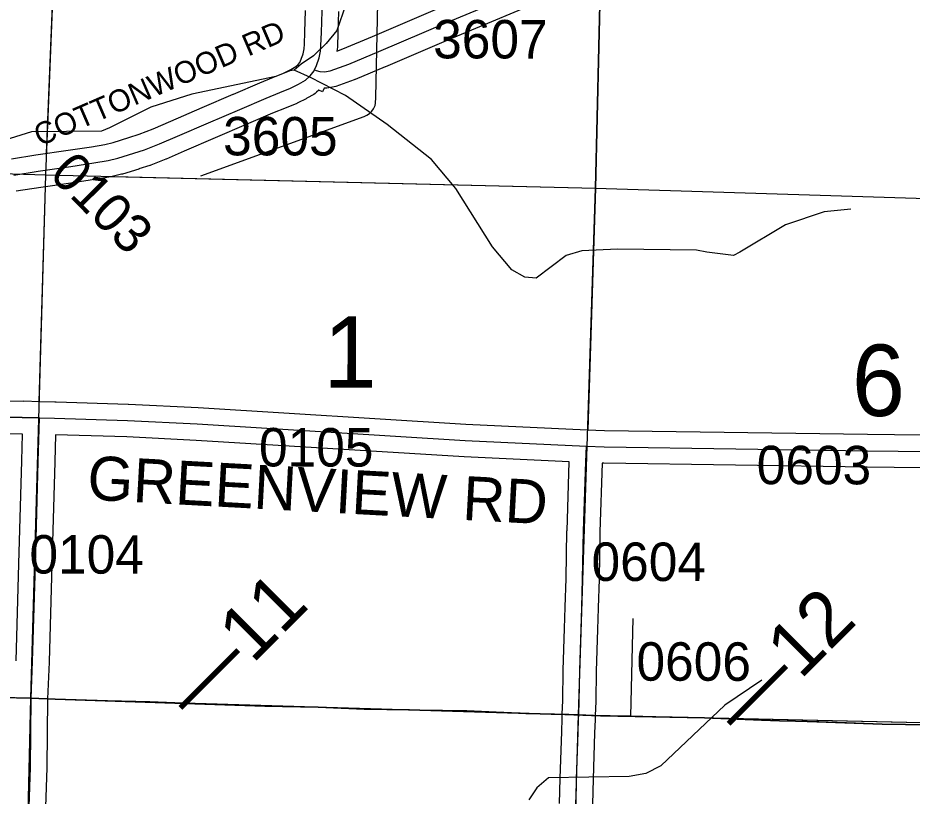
# Model space of a CAD drawing. Extents: x -132.8 to -73.3, y -60 to -26.
# Drawn here: x -117 to -115.373, y -51.589 to -50.173 of the extents above; entities that cross this region are included whole.
import ezdxf

# ---------------------------------------------------------------- set-up
doc = ezdxf.new("R2010")
doc.units = 0
for name, color, linetype in [('tdCoDirctArrow', 7, 'Continuous'), ('tdCoHydroRiver', 7, 'Continuous'), ('tdCoPriCL', 7, 'Continuous'), ('tdCoPrimary', 7, 'Continuous'), ('tdCoPriNonDiv', 7, 'Continuous'), ('tdCoPriNonDivCL', 7, 'Continuous'), ('tdCoSecRdNmbr', 7, 'Continuous'), ('tdCoSecRdTxt', 7, 'Continuous'), ('tdCoSecRteBand', 7, 'Continuous'), ('tdCoSecRteCL', 7, 'Continuous'), ('tdCoSectLine', 7, 'Continuous'), ('tdCoSectLinePart', 7, 'Continuous'), ('tdCoSectNmbr', 7, 'Continuous'), ('tdCoSurfBitum', 7, 'Continuous'), ('tdCoSurfConc', 7, 'Continuous'), ('tdCoSurfConcUnbanded', 7, 'Continuous'), ('tdCoSurfGravel', 7, 'Continuous'), ('tdCoTwpBndry', 7, 'Continuous'), ('tdCoTwpBndryShd', 7, 'Continuous'), ('tdStHwyPriRefPost1', 7, 'Continuous')]:
    doc.layers.add(name, color=color, linetype=linetype)

msp = doc.modelspace()

# ---------------------------------------------------------------- linework, layer by layer
at = {"layer": 'tdCoDirctArrow'}
msp.add_lwpolyline([(-116.6676, -50.4602), (-116.3705, -50.3525), (-116.3655, -50.3502), (-116.3604, -50.3469), (-116.3565, -50.3431), (-116.3534, -50.3385), (-116.3504, -50.3326), (-116.3493, -50.328), (-116.3487, -50.318), (-116.3404, -49.9157)], dxfattribs=at)
at = {"layer": 'tdCoHydroRiver'}
for points in [[(-116.3926, -50.1164), (-116.4199, -50.1962), (-116.4396, -50.2199)], [(-116.4396, -50.2199), (-116.4624, -50.242), (-116.4849, -50.2572), (-116.4978, -50.268)], [(-116.4978, -50.268), (-116.5057, -50.2693), (-116.5312, -50.2797), (-116.6836, -50.3121), (-116.7583, -50.3355), (-116.8335, -50.373), (-116.8478, -50.3789), (-116.9757, -50.3804), (-117.0552, -50.4052), (-117.1027, -50.4087), (-117.1495, -50.4121)], [(-115.4846, -50.521), (-115.5336, -50.526), (-115.6037, -50.5495), (-115.687, -50.5994), (-115.6982, -50.6055), (-115.747, -50.5995), (-115.7658, -50.5958), (-115.9094, -50.5938), (-115.9742, -50.5968), (-116.0028, -50.6056), (-116.0575, -50.6468), (-116.078, -50.6447), (-116.1013, -50.6315), (-116.1366, -50.5896), (-116.2033, -50.4837), (-116.2478, -50.4305), (-116.3282, -50.3669), (-116.4043, -50.3145), (-116.4681, -50.2813), (-116.4978, -50.268)], [(-115.6468, -51.3783), (-115.7142, -51.4239), (-115.8306, -51.5345), (-115.8578, -51.548), (-115.8879, -51.5536), (-116.0348, -51.5561), (-116.0558, -51.5745), (-116.0705, -51.5962)]]:
    msp.add_lwpolyline(points, dxfattribs=at)
at = {"layer": 'tdCoPriCL'}
msp.add_lwpolyline([(-115.3428, -51.4598), (-115.4279, -51.4583), (-115.4925, -51.4561), (-115.5433, -51.4543), (-115.5854, -51.453), (-115.6148, -51.4521), (-115.6473, -51.451), (-115.7512, -51.4472), (-115.8397, -51.445), (-115.886, -51.4441), (-115.9401, -51.443), (-115.9802, -51.4416), (-115.998, -51.441), (-116.076, -51.4388), (-116.1832, -51.4339), (-116.2277, -51.4334), (-116.2691, -51.4329), (-116.288, -51.4325), (-116.3699, -51.4309), (-116.4538, -51.4275), (-116.5504, -51.4257), (-116.5507, -51.4255), (-116.654, -51.4218), (-116.7601, -51.4179), (-116.837, -51.4159), (-116.9322, -51.4129), (-116.9767, -51.4114), (-117.0027, -51.4105)], dxfattribs=at)
at = {"layer": 'tdCoPrimary'}
for p, q in [((-115.5851, -51.453), (-115.5429, -51.4543)), ((-115.5851, -51.453), (-115.5429, -51.4543)), ((-115.5429, -51.4543), (-115.4921, -51.4561)), ((-115.5429, -51.4543), (-115.4921, -51.4561))]:
    msp.add_line(p, q, dxfattribs=at)
for points in [[(-117.0764, -51.407), (-117.0475, -51.4082), (-117.0023, -51.4105), (-116.9763, -51.4114), (-116.9318, -51.4129), (-116.8366, -51.4159), (-116.8031, -51.4167)], [(-117.0764, -51.407), (-117.0475, -51.4082), (-117.0023, -51.4105), (-116.9763, -51.4114), (-116.9318, -51.4129), (-116.8366, -51.4159), (-116.8031, -51.4167)], [(-117.0023, -51.4105), (-116.9763, -51.4114), (-116.9318, -51.4129), (-116.8366, -51.4159), (-116.8031, -51.4167), (-116.7597, -51.4179), (-116.6536, -51.4218), (-116.5501, -51.4257), (-116.5503, -51.4255), (-116.4534, -51.4275), (-116.3695, -51.4309), (-116.2876, -51.4325), (-116.2687, -51.4329), (-116.2274, -51.4334), (-116.1829, -51.4339), (-116.0756, -51.4388), (-115.9977, -51.441), (-115.9799, -51.4416), (-115.9397, -51.443), (-115.8848, -51.4441), (-115.8393, -51.445), (-115.7508, -51.4472), (-115.6469, -51.451), (-115.6144, -51.4521), (-115.5851, -51.453), (-115.5429, -51.4543), (-115.4921, -51.4561), (-115.4275, -51.4583), (-115.3424, -51.4598)], [(-116.8031, -51.4167), (-116.7597, -51.4179), (-116.6536, -51.4218), (-116.5501, -51.4257), (-116.5503, -51.4255), (-116.4534, -51.4275), (-116.3695, -51.4309), (-116.2876, -51.4325)], [(-116.8031, -51.4167), (-116.7597, -51.4179), (-116.6536, -51.4218), (-116.5501, -51.4257), (-116.5503, -51.4255), (-116.4534, -51.4275), (-116.3695, -51.4309), (-116.2876, -51.4325)], [(-116.2876, -51.4325), (-116.2687, -51.4329), (-116.2274, -51.4334)], [(-116.2876, -51.4325), (-116.2687, -51.4329), (-116.2274, -51.4334)], [(-116.2274, -51.4334), (-116.1829, -51.4339), (-116.0756, -51.4388), (-115.9977, -51.441), (-115.9799, -51.4416), (-115.9397, -51.443), (-115.8848, -51.4441), (-115.8393, -51.445), (-115.7508, -51.4472), (-115.6469, -51.451)], [(-116.2274, -51.4334), (-116.1829, -51.4339), (-116.0756, -51.4388), (-115.9977, -51.441), (-115.9799, -51.4416), (-115.9397, -51.443), (-115.8848, -51.4441), (-115.8393, -51.445), (-115.7508, -51.4472), (-115.6469, -51.451)], [(-115.6469, -51.451), (-115.6144, -51.4521), (-115.5851, -51.453)], [(-115.6469, -51.451), (-115.6144, -51.4521), (-115.5851, -51.453)], [(-115.4921, -51.4561), (-115.4275, -51.4583), (-115.3424, -51.4598), (-115.2524, -51.461), (-115.173, -51.4608), (-115.173, -51.4608)], [(-115.4921, -51.4561), (-115.4275, -51.4583), (-115.3424, -51.4598), (-115.2524, -51.461), (-115.173, -51.4608), (-115.173, -51.4608)]]:
    msp.add_lwpolyline(points, dxfattribs=at)
at = {"layer": 'tdCoPriNonDiv'}
msp.add_lwpolyline([(-119.3781, -51.323), (-119.2533, -51.3338), (-119.178, -51.3375), (-119.0616, -51.3419), (-118.9287, -51.352), (-118.8478, -51.3564), (-118.7115, -51.3584), (-118.5248, -51.3661), (-118.2991, -51.3705), (-118.0533, -51.3794), (-117.7549, -51.3875), (-117.6523, -51.392), (-117.5499, -51.3934), (-117.3443, -51.4013), (-117.1376, -51.4043), (-116.9322, -51.4129), (-116.5507, -51.4255), (-116.4538, -51.4275), (-116.2691, -51.4329), (-116.1832, -51.4339), (-115.9401, -51.443), (-115.7512, -51.4472), (-115.4279, -51.4583), (-115.2528, -51.461)], dxfattribs=at)
at = {"layer": 'tdCoPriNonDivCL'}
msp.add_lwpolyline([(-117.0027, -51.4105), (-116.9767, -51.4114), (-116.9322, -51.4129), (-116.837, -51.4159), (-116.8035, -51.4167), (-116.7601, -51.4179), (-116.654, -51.4218), (-116.5504, -51.4257), (-116.5507, -51.4255), (-116.4538, -51.4275), (-116.3699, -51.4309), (-116.288, -51.4325), (-116.2691, -51.4329), (-116.2277, -51.4334), (-116.1832, -51.4339), (-116.076, -51.4388), (-115.998, -51.441), (-115.9802, -51.4416), (-115.9401, -51.443), (-115.8852, -51.4441), (-115.8397, -51.445), (-115.7512, -51.4472), (-115.6473, -51.451), (-115.6148, -51.4521), (-115.5854, -51.453), (-115.5433, -51.4543), (-115.4925, -51.4561), (-115.4279, -51.4583), (-115.3428, -51.4598)], dxfattribs=at)
msp.add_lwpolyline([(-117.0027, -51.4105), (-116.9767, -51.4114), (-116.9322, -51.4129), (-116.837, -51.4159), (-116.8035, -51.4167), (-116.7601, -51.4179), (-116.654, -51.4218), (-116.5504, -51.4257), (-116.5507, -51.4255), (-116.4538, -51.4275), (-116.3699, -51.4309), (-116.288, -51.4325), (-116.2691, -51.4329), (-116.2277, -51.4334), (-116.1832, -51.4339), (-116.076, -51.4388), (-115.998, -51.441), (-115.9802, -51.4416), (-115.9401, -51.443), (-115.8852, -51.4441), (-115.8397, -51.445), (-115.7512, -51.4472), (-115.6473, -51.451), (-115.6148, -51.4521), (-115.5854, -51.453), (-115.5433, -51.4543), (-115.4925, -51.4561), (-115.4279, -51.4583), (-115.3428, -51.4598)], dxfattribs=at)
at = {"layer": 'tdCoSecRteBand'}
for points in [[(-116.0284, -50.1337), (-116.2083, -50.2091), (-116.3315, -50.2619), (-116.3316, -50.2619), (-116.3317, -50.2619), (-116.3867, -50.2851), (-116.3874, -50.2854), (-116.3882, -50.2857), (-116.422, -50.2978), (-116.4248, -50.2988), (-116.4278, -50.2992), (-116.4379, -50.3007), (-116.4409, -50.3012), (-116.4429, -50.301), (-116.446, -50.3076), (-116.4526, -50.3046), (-116.457, -50.3085), (-116.4593, -50.3106), (-116.462, -50.3122), (-116.4746, -50.3194), (-116.4753, -50.3198), (-116.476, -50.3201), (-116.4907, -50.3276), (-116.4918, -50.3281), (-116.4929, -50.3286), (-116.5123, -50.3366), (-116.5367, -50.3467), (-116.5848, -50.3672), (-116.6415, -50.3913), (-116.6979, -50.4157), (-116.7303, -50.4299), (-116.7308, -50.4302), (-116.7313, -50.4304), (-116.7586, -50.4411), (-116.7595, -50.4415), (-116.7604, -50.4417), (-116.7799, -50.448), (-116.7801, -50.4481), (-116.7803, -50.4481), (-116.8098, -50.4572), (-116.8106, -50.4574), (-116.8115, -50.4576), (-116.8289, -50.4619), (-116.83, -50.4622), (-116.8311, -50.4624), (-116.8567, -50.4667), (-116.8569, -50.4667), (-116.8572, -50.4668), (-116.8996, -50.4732), (-116.8996, -50.4732), (-116.8997, -50.4732), (-116.9587, -50.4819), (-117.0031, -50.4887)], [(-116.4197, -50.2333), (-116.4092, -50.2295), (-116.3551, -50.2067), (-116.2318, -50.1539)], [(-117.012, -50.4294), (-116.9677, -50.4225), (-116.9676, -50.4225), (-116.9675, -50.4225), (-116.9085, -50.4138), (-116.8664, -50.4075), (-116.8422, -50.4034), (-116.8266, -50.3996), (-116.7981, -50.3908), (-116.7797, -50.3849), (-116.7538, -50.3747), (-116.7219, -50.3607), (-116.7218, -50.3607), (-116.7218, -50.3607), (-116.6652, -50.3362), (-116.6652, -50.3362), (-116.6651, -50.3362), (-116.6083, -50.312), (-116.6083, -50.3119), (-116.6082, -50.3119), (-116.56, -50.2915), (-116.5599, -50.2914), (-116.5598, -50.2914), (-116.5353, -50.2811), (-116.5352, -50.2811), (-116.5351, -50.2811), (-116.5168, -50.2736), (-116.5038, -50.267), (-116.4947, -50.2617), (-116.4901, -50.2576), (-116.4873, -50.2541), (-116.4819, -50.2403), (-116.4813, -50.2385), (-116.4796, -50.2292), (-116.4787, -50.2209), (-116.4779, -50.1988), (-116.4769, -50.1598)], [(-116.4169, -50.1613), (-116.4179, -50.2005), (-116.4179, -50.2007), (-116.4179, -50.2008), (-116.4188, -50.2243), (-116.4188, -50.2254), (-116.419, -50.2265), (-116.4197, -50.2333)], [(-117.2149, -50.8661), (-116.9899, -50.8705), (-116.9899, -50.8702), (-116.9601, -50.8711), (-116.9332, -50.8716), (-116.9331, -50.8716), (-116.9331, -50.8716), (-116.9303, -50.8716), (-116.9303, -50.8717), (-116.7997, -50.8758), (-116.7995, -50.8758), (-116.7992, -50.8758), (-116.6724, -50.882), (-116.6722, -50.882), (-116.672, -50.882), (-116.185, -50.9123), (-115.9648, -50.9227), (-115.933, -50.9237), (-115.4544, -50.9308), (-115.0098, -50.936)], [(-117.0033, -51.3432), (-116.9984, -51.1668), (-116.9932, -50.9794), (-116.9932, -50.9794), (-116.9932, -50.9793), (-116.9918, -50.9305), (-117.216, -50.9261)], [(-116.0148, -51.6028), (-116.0138, -51.5573), (-116.0138, -51.5572), (-116.0138, -51.557), (-116.0109, -51.4725), (-116.0101, -51.4484), (-116.0101, -51.4484), (-116.0101, -51.4483), (-116.0098, -51.4405), (-116.0089, -51.4153), (-116.0079, -51.3605), (-116.0079, -51.3603), (-116.0079, -51.3601), (-116.0056, -51.2844), (-116.0056, -51.2844), (-116.0056, -51.2844), (-116.0043, -51.2453), (-116.0029, -51.1932), (-116.0012, -51.1068), (-116.0012, -51.1066), (-116.0011, -51.1064), (-115.9972, -50.9812), (-116.188, -50.9722), (-116.1882, -50.9722), (-116.1885, -50.9722), (-116.6756, -50.9419), (-116.8019, -50.9357), (-116.9318, -50.9316), (-116.9332, -50.9811), (-116.9384, -51.1685), (-116.9384, -51.1685), (-116.9384, -51.1685), (-116.9434, -51.3451), (-116.9434, -51.3453), (-116.9434, -51.3456), (-116.9463, -51.4121), (-116.9473, -51.5373), (-116.9473, -51.5377), (-116.9473, -51.5381), (-116.9535, -51.7158)], [(-115.0105, -50.996), (-115.4551, -50.9908), (-115.4552, -50.9908), (-115.4552, -50.9908), (-115.9342, -50.9836), (-115.9344, -50.9836), (-115.9346, -50.9836), (-115.9372, -50.9836), (-115.9412, -51.1082), (-115.9429, -51.1945), (-115.9429, -51.1946), (-115.9429, -51.1947), (-115.9444, -51.247), (-115.9444, -51.2471), (-115.9444, -51.2471), (-115.9456, -51.2863), (-115.9479, -51.3618), (-115.9489, -51.4167), (-115.9489, -51.4169), (-115.9489, -51.4172), (-115.9499, -51.4427), (-115.9502, -51.4505), (-115.951, -51.4745), (-115.9538, -51.5588), (-115.9548, -51.6042)]]:
    msp.add_lwpolyline(points, dxfattribs=at)
at = {"layer": 'tdCoSecRteCL'}
msp.add_line((-115.8848, -51.4441), (-115.8808, -51.2659), dxfattribs=at)
for points in [[(-116.4605, -50.2677), (-116.4567, -50.2597), (-116.4521, -50.2459), (-116.4499, -50.2335), (-116.4488, -50.2232), (-116.4479, -50.1997), (-116.4469, -50.1605), (-116.4441, -50.0442), (-116.4426, -49.9917), (-116.4395, -49.8758), (-116.4376, -49.8162), (-116.4357, -49.7644), (-116.4354, -49.7341), (-116.4344, -49.687), (-116.4326, -49.6461), (-116.4298, -49.5852), (-116.4288, -49.5351), (-116.4269, -49.4812), (-116.4258, -49.4614), (-116.4254, -49.4419)], [(-116.4605, -50.2677), (-116.4578, -50.2688), (-116.4506, -50.2705), (-116.4422, -50.271), (-116.4321, -50.2696), (-116.3983, -50.2575), (-116.3433, -50.2343), (-116.22, -50.1815), (-116.04, -50.1061)], [(-117.0077, -50.4591), (-116.9631, -50.4522), (-116.904, -50.4435), (-116.8617, -50.4371), (-116.8361, -50.4328), (-116.8186, -50.4285), (-116.7891, -50.4195), (-116.7696, -50.4132), (-116.7423, -50.4024), (-116.7099, -50.3882), (-116.6533, -50.3638), (-116.5965, -50.3395), (-116.5483, -50.3191), (-116.5237, -50.3088), (-116.5043, -50.3008), (-116.4895, -50.2934), (-116.477, -50.2862), (-116.4682, -50.2782), (-116.4613, -50.2696), (-116.4605, -50.2677)], [(-117.3088, -50.8943), (-117.2154, -50.8961), (-116.9609, -50.901)], [(-116.9974, -52.3004), (-116.9955, -52.2143), (-116.9921, -52.0389), (-116.9872, -51.8688), (-116.9835, -51.7149), (-116.9773, -51.5371), (-116.9763, -51.4114), (-116.9733, -51.3442), (-116.9684, -51.1677), (-116.9632, -50.9802), (-116.9609, -50.901)], [(-116.9609, -50.901), (-116.9338, -50.9016), (-116.8007, -50.9058), (-116.6739, -50.9119), (-116.1866, -50.9423), (-115.966, -50.9527)], [(-116.0097, -52.4492), (-116.0085, -52.4161), (-116.0062, -52.3325), (-116.0045, -52.247), (-116.0002, -52.1334), (-115.9987, -52.0759), (-115.9969, -52.0094), (-115.9958, -51.9379), (-115.9943, -51.895), (-115.9917, -51.8282), (-115.9885, -51.7343), (-115.9848, -51.6036), (-115.9838, -51.558), (-115.981, -51.4735), (-115.9802, -51.4494), (-115.9799, -51.4416), (-115.9789, -51.4161), (-115.9779, -51.361), (-115.9756, -51.2854), (-115.9744, -51.2462), (-115.9729, -51.1939), (-115.9712, -51.1074), (-115.9672, -50.9809), (-115.966, -50.9527)], [(-115.966, -50.9527), (-115.9337, -50.9536), (-115.4548, -50.9608), (-115.0102, -50.966), (-114.7226, -50.9694), (-114.2948, -50.9734), (-114.2583, -50.9737)]]:
    msp.add_lwpolyline(points, dxfattribs=at)
at = {"layer": 'tdCoSectLine'}
for points in [[(-116.9495, -50.4586), (-116.9091, -49.4603)], [(-115.9494, -50.483), (-115.9254, -49.4919)], [(-117.9423, -50.429), (-116.9495, -50.4586)], [(-116.9767, -51.4114), (-116.9495, -50.4586)], [(-116.9495, -50.4586), (-115.9494, -50.483)], [(-115.9802, -51.4416), (-115.9494, -50.483)], [(-115.9494, -50.483), (-114.9961, -50.5127)], [(-117.9772, -51.3806), (-116.9767, -51.4114)], [(-116.9995, -52.4001), (-116.9767, -51.4114)], [(-116.9767, -51.4114), (-115.9802, -51.4416)], [(-116.0101, -52.4492), (-115.9802, -51.4416)], [(-115.9802, -51.4416), (-115.032, -51.4626)]]:
    msp.add_lwpolyline(points, dxfattribs=at)
at = {"layer": 'tdCoSectLinePart'}
for points in [[(-116.9479, -50.4191), (-116.9103, -49.4902)], [(-115.9494, -50.483), (-115.9401, -50.0966)], [(-116.8284, -50.4616), (-115.9494, -50.483)], [(-116.9613, -50.871), (-116.9502, -50.4805)], [(-115.9636, -50.9227), (-115.9494, -50.483)], [(-115.9494, -50.483), (-114.9961, -50.5127)], [(-116.9467, -51.4123), (-116.0101, -51.4407)], [(-115.9501, -51.4423), (-115.032, -51.4626)]]:
    msp.add_lwpolyline(points, dxfattribs=at)
at = {"layer": 'tdCoSurfBitum'}
msp.add_lwpolyline([(-117.0094, -52.3023), (-116.9974, -52.3004), (-116.9955, -52.2143), (-116.9921, -52.0389), (-116.9872, -51.8688), (-116.9835, -51.7149), (-116.9773, -51.5371), (-116.9763, -51.4114), (-116.9733, -51.3442), (-116.9684, -51.1677), (-116.9632, -50.9802), (-116.9609, -50.901), (-117.2154, -50.8961)], dxfattribs=at)
at = {"layer": 'tdCoSurfConc'}
msp.add_lwpolyline([(-117.0077, -50.4591), (-116.9631, -50.4522), (-116.904, -50.4435), (-116.8617, -50.4371), (-116.8361, -50.4328), (-116.8186, -50.4285), (-116.7891, -50.4195), (-116.7696, -50.4132), (-116.7423, -50.4024), (-116.7099, -50.3882), (-116.6533, -50.3638), (-116.5965, -50.3395), (-116.5483, -50.3191), (-116.5237, -50.3088), (-116.5043, -50.3008), (-116.4895, -50.2934), (-116.477, -50.2862), (-116.4682, -50.2782), (-116.4613, -50.2696), (-116.4605, -50.2677), (-116.4567, -50.2597), (-116.4521, -50.2459), (-116.4499, -50.2335), (-116.4488, -50.2232), (-116.4479, -50.1997), (-116.4469, -50.1605)], dxfattribs=at)
at = {"layer": 'tdCoSurfConcUnbanded'}
msp.add_line((-115.8848, -51.4441), (-115.8808, -51.2659), dxfattribs=at)
at = {"layer": 'tdCoSurfGravel'}
for points in [[(-116.4605, -50.2677), (-116.4578, -50.2688), (-116.4506, -50.2705), (-116.4422, -50.271), (-116.4321, -50.2696), (-116.3983, -50.2575), (-116.3433, -50.2343), (-116.22, -50.1815), (-116.04, -50.1061), (-115.9337, -50.0614)], [(-116.9609, -50.901), (-116.9338, -50.9016), (-116.8007, -50.9058), (-116.6739, -50.9119), (-116.1866, -50.9423), (-115.966, -50.9527)], [(-115.9799, -51.4416), (-115.9789, -51.4161), (-115.9779, -51.361), (-115.9756, -51.2854), (-115.9744, -51.2462), (-115.9729, -51.1939), (-115.9712, -51.1074), (-115.9672, -50.9809), (-115.966, -50.9527)], [(-115.966, -50.9527), (-115.9337, -50.9536), (-115.4548, -50.9608), (-115.0102, -50.966)], [(-115.9848, -51.6036), (-115.9838, -51.558), (-115.981, -51.4735), (-115.9802, -51.4494), (-115.9799, -51.4416)]]:
    msp.add_lwpolyline(points, dxfattribs=at)
at = {"layer": 'tdCoTwpBndry'}
for points in [[(-115.9401, -50.0964), (-115.9494, -50.483), (-115.9636, -50.9228)], [(-116.8271, -50.4616), (-115.9494, -50.483), (-114.9961, -50.5127), (-114.2793, -50.5289)]]:
    msp.add_lwpolyline(points, dxfattribs=at)
at = {"layer": 'tdCoTwpBndryShd'}
for points in [[(-116.128, -56.4384), (-116.0982, -55.4391), (-116.0724, -54.4424), (-116.042, -53.4425), (-116.0101, -52.4492), (-115.9802, -51.4416), (-115.9494, -50.483), (-115.9254, -49.4919), (-115.9017, -48.4949), (-115.8779, -47.4977), (-115.834, -46.4945), (-115.8159, -45.5058), (-115.7834, -44.5349), (-115.7494, -43.5344), (-115.7226, -42.5378), (-115.6969, -41.5376), (-115.6667, -40.5277)], [(-120.9191, -50.3467), (-120.4215, -50.3572), (-119.924, -50.3677), (-119.4305, -50.3843), (-118.9369, -50.3941), (-117.9423, -50.429), (-116.9495, -50.4586), (-115.9494, -50.483), (-114.9961, -50.5127), (-114.0011, -50.5352), (-112.9865, -50.5642), (-112.0017, -50.5957), (-111.0051, -50.628), (-110.6406, -50.6427), (-110.0099, -50.6583), (-109.0466, -50.682), (-108.0484, -50.7057), (-107.0549, -50.7359), (-106.0586, -50.7581), (-105.063, -50.7875), (-104.0667, -50.813)]]:
    msp.add_lwpolyline(points, dxfattribs=at)

# ---------------------------------------------------------------- texts
at = {"layer": 'tdCoSecRdNmbr'}
for s, rotation, p in [('3607', 359.9123, (-116.2447, -50.2467)), ('3605', 359.9121, (-116.6268, -50.4232)), ('0103', 314.9119, (-116.9452, -50.4602)), ('0105', 359.9123, (-116.5616, -50.9894)), ('0603', 359.913, (-115.6561, -51.0217)), ('0104', 359.912, (-116.9792, -51.1843)), ('0604', 359.9128, (-115.9566, -51.1977)), ('0606', 359.9128, (-115.8748, -51.3793))]:
    msp.add_text(s, height=0.07, rotation=rotation, dxfattribs=at).set_placement(p)
at = {"layer": 'tdCoSecRdTxt'}
for s, height, rotation, p in [('COTTONWOOD RD', 0.04, 23.3647, (-116.9602, -50.4074)), ('GREENVIEW RD', 0.08, 356.8917, (-116.8753, -51.0495))]:
    msp.add_text(s, height=height, rotation=rotation, dxfattribs=at).set_placement(p)
at = {"layer": 'tdCoSectNmbr'}
for s, rotation, p in [('1', 359.9123, (-116.4443, -50.8461)), ('6', 359.913, (-115.483, -50.8975))]:
    msp.add_text(s, height=0.13, rotation=rotation, dxfattribs=at).set_placement(p)
at = {"layer": 'tdStHwyPriRefPost1'}
for s, p in [('‒‒11', (-116.6783, -51.4549)), ('‒‒12', (-115.6814, -51.4838))]:
    msp.add_text(s, height=0.1, rotation=45, dxfattribs=at).set_placement(p)

doc.saveas('drawing.dxf')
